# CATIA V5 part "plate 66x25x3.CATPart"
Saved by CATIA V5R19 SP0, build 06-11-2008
Part number: plate 66x25x3
Bounding box of the stored display mesh (mm): x -66 to 0, y 0 to 3, z 0 to 25
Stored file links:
  D:\AUTO BATCH (BHEL)\Collecting Hopper 2\plate 66x25x3.CATPart
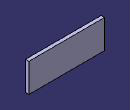
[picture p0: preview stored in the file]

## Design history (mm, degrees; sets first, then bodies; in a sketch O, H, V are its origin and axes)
SheetMetalParameters1: BendRadius 3, ReliefAxialLength 2, ReliefRadialLength 1, MinimumBendRadius 0, Thickness 3, KFactor 0.325257 {= log(min(100,max(20*SheetMetalParameters1.BendRadius,SheetMetalParameters1.Thickness)/SheetMetalParameters1.Thickness))/log(100)/2}
Set1
  Sketch1 on zx-plane, origin (0, 0, 0), H (-1, 0, 0), V (0, 0, 1)
    line L1 (0, 0) -> (66, 0)
    line L2 (66, 0) -> (66, 25)
    line L3 (66, 25) -> (0, 25)
    line L4 (0, 25) -> (0, 0)
    length L1 = 66
    length L2 = 25
    horizontal: L1 H, L3 H
    vertical: L2 V, L4 V
Body1 (main body)
  Wall1: Thickness 3, Profile Sketch1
